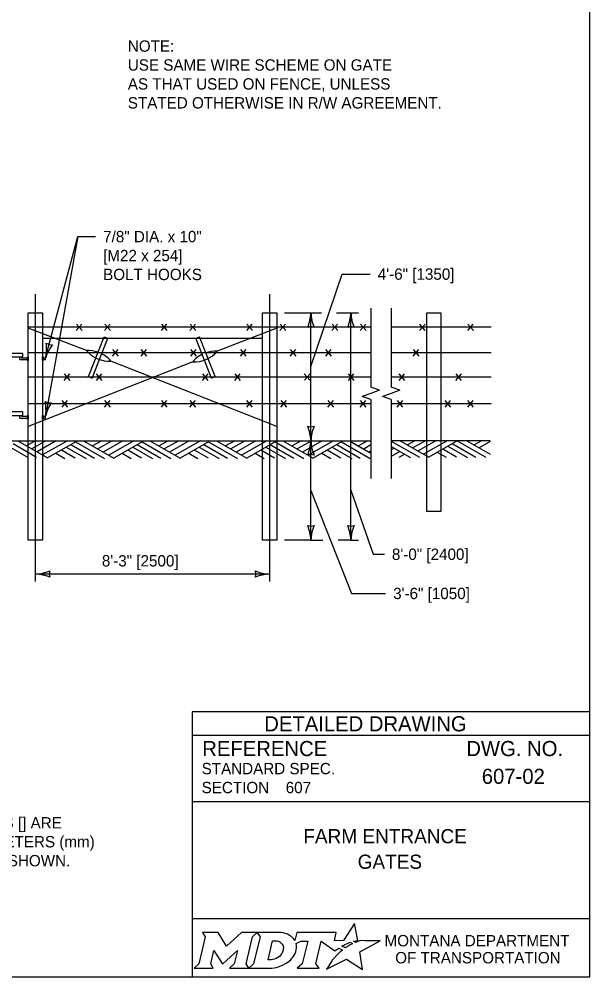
# Model space of a CAD drawing. Extents: x 49991.4 to 50021, y 49987.6 to 50011.4.
# Drawn here: x 50005.6 to 50008.61, y 50000.06 to 50005.12 of the extents above; entities that cross this region are included whole.
import ezdxf

# ---------------------------------------------------------------- set-up
doc = ezdxf.new("R2010")
doc.units = 0
for name, color, linetype in [('Level 1', 7, 'Continuous'), ('Level 2', 7, 'Continuous'), ('Level 3', 7, 'Continuous'), ('Level 4', 7, 'Continuous'), ('Level 5', 7, 'Continuous'), ('Level 6', 7, 'Continuous')]:
    doc.layers.add(name, color=color, linetype=linetype)

msp = doc.modelspace()

# ---------------------------------------------------------------- linework, layer by layer
at = {"layer": 'Level 1'}
for p, q in [((50005.6494, 50003.5711), (50005.7244, 50003.5711)), ((50005.6494, 50002.8961), (50005.6494, 50003.5711)), ((50005.7244, 50003.5711), (50005.7244, 50002.8961)), ((50006.8869, 50003.5711), (50006.9619, 50003.5711)), ((50006.8869, 50002.8961), (50006.8869, 50003.5711)), ((50006.9619, 50003.5711), (50006.9619, 50002.8961)), ((50007.7534, 50002.8961), (50007.7534, 50003.5711)), ((50007.7534, 50003.5711), (50007.8284, 50003.5711)), ((50007.8284, 50003.5711), (50007.8284, 50002.8961)), ((50007.4579, 50003.4961), (50005.6494, 50003.4961)), ((50005.9575, 50003.3719), (50005.6494, 50003.4906)), ((50006.8869, 50003.4961), (50005.7244, 50003.4961)), ((50005.9027, 50003.478), (50005.932, 50003.5127)), ((50005.9334, 50003.478), (50005.904, 50003.5127)), ((50006.0527, 50003.478), (50006.082, 50003.5127)), ((50006.0834, 50003.478), (50006.054, 50003.5127)), ((50006.3527, 50003.478), (50006.382, 50003.5127)), ((50006.3834, 50003.478), (50006.354, 50003.5127)), ((50006.5027, 50003.478), (50006.532, 50003.5127)), ((50006.5334, 50003.478), (50006.504, 50003.5127)), ((50006.9619, 50003.4909), (50006.6468, 50003.3684)), ((50006.8027, 50003.478), (50006.832, 50003.5127)), ((50006.8334, 50003.478), (50006.804, 50003.5127)), ((50006.9783, 50003.478), (50007.0076, 50003.5127)), ((50007.009, 50003.478), (50006.9796, 50003.5127)), ((50007.2527, 50003.478), (50007.282, 50003.5127)), ((50007.2834, 50003.478), (50007.254, 50003.5127)), ((50007.4027, 50003.478), (50007.432, 50003.5127)), ((50007.4334, 50003.478), (50007.404, 50003.5127)), ((50008.0929, 50003.4961), (50007.5658, 50003.4961)), ((50007.715, 50003.478), (50007.7443, 50003.5127)), ((50007.7457, 50003.478), (50007.7163, 50003.5127)), ((50007.97, 50003.478), (50007.9993, 50003.5127)), ((50008.0007, 50003.478), (50007.9713, 50003.5127)), ((50006.8869, 50003.4361), (50005.7244, 50003.4361)), ((50005.9674, 50003.2345), (50006.0506, 50003.4445)), ((50005.986, 50003.2271), (50006.0692, 50003.4371)), ((50006.0506, 50003.4445), (50006.0692, 50003.4371)), ((50006.5344, 50003.4371), (50006.553, 50003.4445)), ((50006.6177, 50003.2271), (50006.5344, 50003.4371)), ((50006.6362, 50003.2345), (50006.553, 50003.4445)), ((50006.0948, 50003.343), (50006.1242, 50003.3777)), ((50006.1255, 50003.343), (50006.0962, 50003.3777)), ((50006.2448, 50003.343), (50006.2742, 50003.3777)), ((50006.2755, 50003.343), (50006.2462, 50003.3777)), ((50006.5073, 50003.343), (50006.5367, 50003.3777)), ((50006.538, 50003.343), (50006.5087, 50003.3777)), ((50006.7698, 50003.343), (50006.7992, 50003.3777)), ((50006.8005, 50003.343), (50006.7712, 50003.3777)), ((50007.0331, 50003.343), (50007.0625, 50003.3777)), ((50007.0638, 50003.343), (50007.0345, 50003.3777)), ((50007.2198, 50003.343), (50007.2492, 50003.3777)), ((50007.2505, 50003.343), (50007.2212, 50003.3777)), ((50007.6821, 50003.343), (50007.7115, 50003.3777)), ((50007.7128, 50003.343), (50007.6835, 50003.3777)), ((50005.6052, 50003.3246), (50005.6052, 50003.3389)), ((50005.6052, 50003.3246), (50005.6494, 50003.3246)), ((50005.6146, 50003.334), (50005.6146, 50003.3389)), ((50005.6146, 50003.334), (50005.6494, 50003.334)), ((50007.4579, 50003.3611), (50005.6494, 50003.3611)), ((50005.7244, 50003.334), (50005.7413, 50003.334)), ((50005.7244, 50003.3246), (50005.7413, 50003.3246)), ((50005.7413, 50003.3246), (50005.7413, 50003.334)), ((50006.9619, 50002.9711), (50006.086, 50003.3168)), ((50008.0929, 50003.3611), (50007.5658, 50003.3611)), ((50006.5184, 50003.3133), (50005.6494, 50002.9711)), ((50007.4579, 50003.2321), (50005.6494, 50003.2321)), ((50005.8398, 50003.214), (50005.8692, 50003.2487)), ((50005.8705, 50003.214), (50005.8412, 50003.2487)), ((50005.9674, 50003.2345), (50005.986, 50003.2271)), ((50006.0092, 50003.214), (50006.0386, 50003.2487)), ((50006.0399, 50003.214), (50006.0106, 50003.2487)), ((50006.5692, 50003.214), (50006.5986, 50003.2487)), ((50006.5999, 50003.214), (50006.5706, 50003.2487)), ((50006.6177, 50003.2271), (50006.6362, 50003.2345)), ((50006.7398, 50003.214), (50006.7692, 50003.2487)), ((50006.7705, 50003.214), (50006.7412, 50003.2487)), ((50007.1359, 50003.2154), (50007.1066, 50003.2501)), ((50007.1077, 50003.2154), (50007.1371, 50003.2501)), ((50007.3398, 50003.214), (50007.3692, 50003.2487)), ((50007.3705, 50003.214), (50007.3412, 50003.2487)), ((50008.0929, 50003.2321), (50007.5658, 50003.2321)), ((50007.6071, 50003.214), (50007.6365, 50003.2487)), ((50007.6378, 50003.214), (50007.6085, 50003.2487)), ((50007.9071, 50003.214), (50007.9365, 50003.2487)), ((50007.9378, 50003.214), (50007.9085, 50003.2487)), ((50007.4579, 50003.0911), (50005.6494, 50003.0911)), ((50005.8277, 50003.073), (50005.857, 50003.1077)), ((50005.8584, 50003.073), (50005.829, 50003.1077)), ((50006.0527, 50003.073), (50006.082, 50003.1077)), ((50006.0834, 50003.073), (50006.054, 50003.1077)), ((50006.3527, 50003.073), (50006.382, 50003.1077)), ((50006.3834, 50003.073), (50006.354, 50003.1077)), ((50006.5027, 50003.073), (50006.532, 50003.1077)), ((50006.5334, 50003.073), (50006.504, 50003.1077)), ((50006.8027, 50003.073), (50006.832, 50003.1077)), ((50006.8334, 50003.073), (50006.804, 50003.1077)), ((50006.9833, 50003.073), (50007.0126, 50003.1077)), ((50007.014, 50003.073), (50006.9846, 50003.1077)), ((50007.2318, 50003.073), (50007.2611, 50003.1077)), ((50007.2625, 50003.073), (50007.2331, 50003.1077)), ((50007.4027, 50003.073), (50007.432, 50003.1077)), ((50007.4334, 50003.073), (50007.404, 50003.1077)), ((50008.0929, 50003.0911), (50007.5658, 50003.0911)), ((50007.5972, 50003.073), (50007.6265, 50003.1077)), ((50007.6279, 50003.073), (50007.5985, 50003.1077)), ((50007.85, 50003.073), (50007.8793, 50003.1077)), ((50007.8807, 50003.073), (50007.8513, 50003.1077)), ((50007.97, 50003.073), (50007.9993, 50003.1077)), ((50008.0007, 50003.073), (50007.9713, 50003.1077)), ((50005.6052, 50003.0156), (50005.6052, 50003.0299)), ((50005.6052, 50003.0156), (50005.6494, 50003.0156)), ((50005.6146, 50003.025), (50005.6146, 50003.0299)), ((50005.6146, 50003.025), (50005.6494, 50003.025)), ((50005.7244, 50003.025), (50005.7413, 50003.025)), ((50005.7244, 50003.0156), (50005.7413, 50003.0156)), ((50005.7413, 50003.0156), (50005.7413, 50003.025)), ((50004.5739, 50002.8961), (50007.4579, 50002.8961)), ((50005.5455, 50002.8676), (50005.6495, 50002.8075)), ((50005.5692, 50002.8812), (50005.6935, 50002.8094)), ((50005.5941, 50002.8961), (50005.7517, 50002.8051)), ((50005.686, 50002.8961), (50005.64, 50002.8696)), ((50005.742, 50002.8961), (50005.668, 50002.8534)), ((50005.7973, 50002.8961), (50005.6957, 50002.8375)), ((50005.8563, 50002.8961), (50005.7252, 50002.8204)), ((50005.8998, 50002.8906), (50005.7517, 50002.8051)), ((50005.8504, 50002.8621), (50005.9544, 50002.802)), ((50005.8741, 50002.8757), (50005.9984, 50002.8039)), ((50005.899, 50002.8906), (50006.0512, 50002.8027)), ((50005.9405, 50002.8961), (50006.1005, 50002.8037)), ((50006.0371, 50002.8961), (50005.9888, 50002.8682)), ((50006.0931, 50002.8961), (50006.0167, 50002.8521)), ((50006.1484, 50002.8961), (50006.0444, 50002.8361)), ((50006.2074, 50002.8961), (50006.074, 50002.819)), ((50006.2509, 50002.8906), (50006.1005, 50002.8037)), ((50006.2015, 50002.8621), (50006.3055, 50002.802)), ((50006.2252, 50002.8757), (50006.3495, 50002.8039)), ((50006.2501, 50002.8906), (50006.4023, 50002.8027)), ((50006.2916, 50002.8961), (50006.4516, 50002.8037)), ((50006.3882, 50002.8961), (50006.3399, 50002.8682)), ((50006.4442, 50002.8961), (50006.3678, 50002.8521)), ((50006.4995, 50002.8961), (50006.3955, 50002.8361)), ((50006.5585, 50002.8961), (50006.4251, 50002.819)), ((50006.602, 50002.8906), (50006.4516, 50002.8037)), ((50006.5526, 50002.8621), (50006.6566, 50002.802)), ((50006.5763, 50002.8757), (50006.7006, 50002.8039)), ((50006.6012, 50002.8906), (50006.7534, 50002.8027)), ((50006.6427, 50002.8961), (50006.8027, 50002.8037)), ((50006.7393, 50002.8961), (50006.691, 50002.8682)), ((50006.7953, 50002.8961), (50006.7189, 50002.8521)), ((50006.8506, 50002.8961), (50006.7466, 50002.8361)), ((50006.9096, 50002.8961), (50006.7762, 50002.819)), ((50006.9531, 50002.8906), (50006.8027, 50002.8037)), ((50006.9037, 50002.8621), (50007.0077, 50002.802)), ((50006.9274, 50002.8757), (50007.0517, 50002.8039)), ((50006.9523, 50002.8906), (50007.1045, 50002.8027)), ((50006.9938, 50002.8961), (50007.1537, 50002.8037)), ((50007.0904, 50002.8961), (50007.0421, 50002.8682)), ((50007.1464, 50002.8961), (50007.07, 50002.8521)), ((50007.2017, 50002.8961), (50007.0976, 50002.8362)), ((50007.2607, 50002.8961), (50007.1273, 50002.819)), ((50007.3038, 50002.8904), (50007.1537, 50002.8037)), ((50007.2548, 50002.8621), (50007.3588, 50002.802)), ((50007.2784, 50002.8757), (50007.4028, 50002.8039)), ((50007.3034, 50002.8906), (50007.4556, 50002.8027)), ((50007.3449, 50002.8961), (50007.4579, 50002.8308)), ((50007.4415, 50002.8961), (50007.3931, 50002.8682)), ((50007.4579, 50002.8733), (50007.4211, 50002.852)), ((50008.0891, 50002.8961), (50007.5658, 50002.8961)), ((50007.5658, 50002.894), (50007.7144, 50002.8082)), ((50007.5658, 50002.8655), (50007.6673, 50002.8069)), ((50007.6132, 50002.8961), (50007.7637, 50002.8092)), ((50007.6907, 50002.8961), (50007.652, 50002.8737)), ((50007.7468, 50002.8961), (50007.6799, 50002.8576)), ((50007.802, 50002.8961), (50007.7076, 50002.8416)), ((50007.8611, 50002.8961), (50007.7372, 50002.8245)), ((50007.9141, 50002.8961), (50007.7637, 50002.8092)), ((50007.8647, 50002.8676), (50007.9687, 50002.8075)), ((50007.8884, 50002.8812), (50008.0127, 50002.8094)), ((50007.9133, 50002.8961), (50008.0655, 50002.8082)), ((50007.9643, 50002.8961), (50008.0891, 50002.824)), ((50008.0418, 50002.8961), (50008.0031, 50002.8737)), ((50008.0891, 50002.891), (50008.031, 50002.8576)), ((50005.7948, 50002.83), (50005.8419, 50002.8027)), ((50005.8241, 50002.8469), (50005.8963, 50002.8051)), ((50006.1459, 50002.83), (50006.193, 50002.8027)), ((50006.1752, 50002.8469), (50006.2474, 50002.8051)), ((50006.497, 50002.83), (50006.5441, 50002.8027)), ((50006.5263, 50002.8469), (50006.5985, 50002.8051)), ((50006.8481, 50002.83), (50006.8952, 50002.8027)), ((50006.8774, 50002.8469), (50006.9496, 50002.8051)), ((50007.1992, 50002.83), (50007.2463, 50002.8027)), ((50007.2284, 50002.8469), (50007.3007, 50002.8051)), ((50007.4579, 50002.8415), (50007.4486, 50002.8361)), ((50007.5816, 50002.8564), (50007.5658, 50002.8472)), ((50007.6112, 50002.8393), (50007.5658, 50002.8131)), ((50007.6376, 50002.824), (50007.6069, 50002.8063)), ((50007.8091, 50002.8355), (50007.8562, 50002.8082)), ((50007.8384, 50002.8524), (50007.9106, 50002.8106))]:
    msp.add_line(p, q, dxfattribs=at)
for points in [[(50008.6146, 50011.2628), (50000.3356, 50011.2628), (50000.3356, 50000.0624), (50008.6146, 50000.0624)], [(50005.621, 50003.3389), (50005.621, 50003.3573), (50005.5547, 50003.3573), (50005.5547, 50003.3389)], [(50005.6494, 50003.3386), (50005.6494, 50003.3193), (50005.645, 50003.3193), (50005.645, 50003.3386)], [(50005.7288, 50003.3388), (50005.7288, 50003.3195), (50005.7244, 50003.3195), (50005.7244, 50003.3388)], [(50005.621, 50003.0299), (50005.621, 50003.0483), (50005.5547, 50003.0483), (50005.5547, 50003.0299)], [(50005.6494, 50003.0296), (50005.6494, 50003.0103), (50005.645, 50003.0103), (50005.645, 50003.0296)], [(50005.7288, 50003.0298), (50005.7288, 50003.0105), (50005.7244, 50003.0105), (50005.7244, 50003.0298)]]:
    msp.add_lwpolyline(points, close=True, dxfattribs=at)
for centre, start, end in [((50005.9672, 50003.2172), 70.692, 93.5951), ((50006.0763, 50003.4716), 220.0078, 273.5951), ((50006.528, 50003.468), 266.4347, 320.0376), ((50006.6372, 50003.2137), 86.4347, 109.12), ((50005.9672, 50003.2172), 40.0078, 63.2871), ((50006.6372, 50003.2137), 116.511, 140.0376)]:
    msp.add_arc(centre, 0.155, start, end, dxfattribs=at)
at = {"layer": 'Level 2'}
for p, q in [((50008.6146, 50001.4624), (50006.5146, 50001.4624)), ((50006.5146, 50001.4624), (50006.5146, 50000.0624)), ((50008.6146, 50001.3374), (50006.5146, 50001.3374)), ((50008.2507, 50001.1223), (50008.2507, 50001.1223)), ((50007.0089, 50001.0629), (50007.0089, 50001.0629)), ((50008.6146, 50000.9874), (50006.5146, 50000.9874)), ((50007.5646, 50000.7383), (50007.5646, 50000.7383)), ((50008.6146, 50000.3693), (50006.5146, 50000.3693))]:
    msp.add_line(p, q, dxfattribs=at)
for points in [[(50007.3771, 50000.2447), (50007.3668, 50000.2503), (50007.3784, 50000.2531), (50007.39, 50000.2551), (50007.3726, 50000.3452), (50007.3131, 50000.2539), (50007.2658, 50000.2532), (50007.2761, 50000.2973), (50007.0669, 50000.2974), (50007.0568, 50000.2549), (50007.051, 50000.2632)], [(50006.5701, 50000.2974), (50006.5842, 50000.274), (50006.5507, 50000.1307), (50006.525, 50000.1082), (50006.6266, 50000.1082), (50006.6131, 50000.131), (50006.6293, 50000.2011), (50006.673, 50000.1321), (50006.6783, 50000.1321), (50006.7534, 50000.2016), (50006.737, 50000.1305), (50006.7123, 50000.1085), (50006.8139, 50000.1085), (50006.8001, 50000.1318), (50006.8333, 50000.2742)], [(50006.8333, 50000.2742), (50006.8586, 50000.2974), (50006.7762, 50000.2974), (50006.6966, 50000.2244), (50006.6521, 50000.2971), (50006.5701, 50000.2974)], [(50006.9722, 50000.2974), (50006.8586, 50000.2974), (50006.8733, 50000.2745), (50006.8394, 50000.1307), (50006.8139, 50000.1085), (50006.9245, 50000.1085)], [(50006.9962, 50000.2107), (50006.995, 50000.2026), (50006.9918, 50000.1933), (50006.9876, 50000.1851), (50006.982, 50000.1776), (50006.9755, 50000.1707), (50006.9676, 50000.1644), (50006.9593, 50000.1597), (50006.9502, 50000.1558), (50006.9411, 50000.1535), (50006.9319, 50000.1526), (50006.916, 50000.1526), (50006.9396, 50000.2526), (50006.9556, 50000.2526), (50006.9632, 50000.252), (50006.9708, 50000.2501), (50006.9774, 50000.2471), (50006.9835, 50000.2429), (50006.9883, 50000.2379), (50006.992, 50000.2319), (50006.9947, 50000.2257), (50006.9963, 50000.2183), (50006.9963, 50000.2153), (50006.9962, 50000.2107)], [(50007.0636, 50000.2383), (50007.0882, 50000.2514), (50007.1251, 50000.2514), (50007.0965, 50000.1309), (50007.069, 50000.1082), (50007.1852, 50000.1082), (50007.1682, 50000.1311), (50007.1964, 50000.2513), (50007.2677, 50000.1996), (50007.2888, 50000.2147), (50007.3085, 50000.2038)], [(50007.2527, 50000.1479), (50007.2374, 50000.1235), (50007.2327, 50000.116), (50007.2269, 50000.1074), (50007.2246, 50000.1031), (50007.3299, 50000.1562), (50007.4138, 50000.1011), (50007.4007, 50000.1938), (50007.5076, 50000.2522), (50007.4583, 50000.253), (50007.4282, 50000.2534), (50007.4074, 50000.2537), (50007.4006, 50000.2522), (50007.3957, 50000.251), (50007.3873, 50000.2487), (50007.3771, 50000.2447)], [(50007.3267, 50000.2171), (50007.3243, 50000.2154), (50007.306, 50000.225), (50007.3163, 50000.2307), (50007.3204, 50000.2329), (50007.329, 50000.2369), (50007.3347, 50000.2395), (50007.3426, 50000.2425), (50007.3499, 50000.2452), (50007.3617, 50000.2378), (50007.3577, 50000.2357), (50007.3531, 50000.2332), (50007.3489, 50000.231), (50007.3439, 50000.2281), (50007.342, 50000.227), (50007.3393, 50000.2254), (50007.3368, 50000.224), (50007.3345, 50000.2224), (50007.3319, 50000.2206), (50007.3292, 50000.2188), (50007.3267, 50000.2171)], [(50006.9702, 50000.1158), (50006.9786, 50000.1184), (50006.9916, 50000.1238), (50007.012, 50000.1348)], [(50007.2666, 50000.164), (50007.2666, 50000.164)]]:
    msp.add_lwpolyline(points, dxfattribs=at)
for centre, radius, start, end in [((50006.9953, 50000.219), 0.0709, 339.5329, 15.8582), ((50006.9513, 50000.2363), 0.1183, 300.9103, 339.1383)]:
    msp.add_arc(centre, radius, start, end, dxfattribs=at)
for centre, major_axis, ratio, start_param, end_param in [((50006.9701, 50000.25), (0.0834, -0.0037), 0.568097, 0.61298, 1.570796), ((50007.0257, 50000.2573), (0.0361, -0.0295), 0.469099, 1.225588, 1.570796), ((50007.2764, 50000.1742), (-0.0098, -0.0102), 0.016458, 3.141593, 6.279097), ((50007.2974, 50000.1941), (-0.0112, -0.0097), 0.021651, 3.157348, 6.283185), ((50007.2597, 50000.1559), (-0.00694, -0.00806), 0.008222, 0, 3.137361), ((50006.9248, 50000.2568), (0, 0.1484), 0.987302, 3.139398, 3.456847)]:
    msp.add_ellipse(centre, major_axis=major_axis, ratio=ratio, start_param=start_param, end_param=end_param, dxfattribs=at)
at = {"layer": 'Level 3'}
for p, q in [((50005.7413, 50003.334), (50005.9113, 50003.9746)), ((50005.9113, 50003.9746), (50005.7413, 50003.025)), ((50005.9113, 50003.9746), (50006.0048, 50003.9746)), ((50007.0019, 50003.5711), (50007.1974, 50003.5711)), ((50007.1418, 50002.8961), (50007.1418, 50003.5711)), ((50007.2774, 50003.5712), (50007.393, 50003.5711)), ((50007.353, 50002.3711), (50007.353, 50003.5711)), ((50007.1418, 50002.3711), (50007.1418, 50002.8961)), ((50007.1418, 50002.3711), (50007.0019, 50002.3711)), ((50007.1418, 50002.3711), (50007.205, 50002.3711)), ((50007.353, 50002.3711), (50007.2851, 50002.3711)), ((50007.353, 50002.3711), (50007.393, 50002.3711)), ((50006.9244, 50002.1911), (50005.6869, 50002.1911))]:
    msp.add_line(p, q, dxfattribs=at)
for points in [[(50007.1418, 50003.2878), (50007.3067, 50003.7765), (50007.455, 50003.7765)], [(50007.1418, 50002.6336), (50007.3562, 50002.0887), (50007.5361, 50002.0887), (50007.5361, 50002.0887)], [(50007.353, 50002.6342), (50007.4701, 50002.2958), (50007.5297, 50002.2958)]]:
    msp.add_lwpolyline(points, dxfattribs=at)
for centre, radius, start, end in [((50006.9197, 50003.5803), 0.2223, 337.456, 357.6395), ((50007.3745, 50003.5826), 0.233, 182.8273, 202.0772), ((50007.1309, 50003.5803), 0.2223, 337.456, 357.6395), ((50007.5857, 50003.5826), 0.233, 182.8273, 202.0772), ((50007.1418, 50003.4429), 0.0548, 72.1388, 107.8612), ((50007.353, 50003.4429), 0.0548, 72.1388, 107.8612), ((50005.5134, 50003.3826), 0.233, 347.9649, 7.2148), ((50005.5134, 50003.3826), 0.233, 347.9649, 7.2148), ((50005.9537, 50003.2682), 0.2223, 142.5936, 162.7772), ((50005.9537, 50003.2682), 0.2223, 142.5936, 162.7772), ((50005.7742, 50003.4579), 0.0548, 237.2765, 272.9988), ((50005.7742, 50003.4579), 0.0548, 237.2765, 272.9988), ((50005.7639, 50003.1512), 0.0548, 241.9891, 277.7115), ((50005.5102, 50003.0547), 0.233, 352.6776, 11.9274), ((50005.9583, 50002.9768), 0.2223, 147.3063, 167.4898), ((50007.1418, 50003.0243), 0.0548, 252.1388, 287.8612), ((50006.9091, 50002.8846), 0.233, 2.8273, 22.0772), ((50007.3639, 50002.8869), 0.2223, 157.456, 177.6395), ((50006.9197, 50002.9053), 0.2223, 337.456, 357.6395), ((50007.3745, 50002.9076), 0.233, 182.8273, 202.0772), ((50007.1418, 50002.7679), 0.0548, 72.1388, 107.8612), ((50007.1418, 50002.4993), 0.0548, 252.1388, 287.8612), ((50006.9091, 50002.3596), 0.233, 2.8273, 22.0772), ((50007.3639, 50002.362), 0.2223, 157.456, 177.6395), ((50007.353, 50002.4993), 0.0548, 252.1388, 287.8612), ((50007.1202, 50002.3596), 0.233, 2.8273, 22.0772), ((50007.5751, 50002.362), 0.2223, 157.456, 177.6395), ((50005.6754, 50002.4238), 0.233, 272.8273, 292.0772), ((50005.8151, 50002.1911), 0.0548, 162.1388, 197.8612), ((50006.9336, 50002.4132), 0.2223, 247.456, 267.6395), ((50006.7962, 50002.1911), 0.0548, 342.1388, 17.8612), ((50005.6777, 50001.969), 0.2223, 67.456, 87.6395), ((50006.9359, 50001.9584), 0.233, 92.8273, 112.0772)]:
    msp.add_arc(centre, radius, start, end, dxfattribs=at)
at = {"layer": 'Level 4'}
for p, q in [((50005.6494, 50002.3711), (50005.6494, 50002.8961)), ((50005.7244, 50002.8961), (50005.7244, 50002.3711)), ((50006.8869, 50002.3711), (50006.8869, 50002.8961)), ((50006.9619, 50002.8961), (50006.9619, 50002.3711)), ((50007.7534, 50002.5211), (50007.7534, 50002.8961)), ((50007.8284, 50002.8961), (50007.8284, 50002.5211)), ((50007.8284, 50002.5211), (50007.7534, 50002.5211)), ((50005.7244, 50002.3711), (50005.6494, 50002.3711)), ((50006.9619, 50002.3711), (50006.8869, 50002.3711))]:
    msp.add_line(p, q, dxfattribs=at)
at = {"layer": 'Level 5'}
for p, q in [((50005.6869, 50002.1511), (50005.6869, 50003.6711)), ((50006.9244, 50002.1511), (50006.9244, 50003.6711))]:
    msp.add_line(p, q, dxfattribs=at)
at = {"layer": 'Level 6'}
for p, q in [((50007.4579, 50003.5961), (50007.4579, 50003.1785)), ((50007.5658, 50003.5961), (50007.5658, 50003.1785)), ((50007.5036, 50003.1623), (50007.4579, 50003.1785)), ((50007.5036, 50003.1623), (50007.4579, 50003.1461)), ((50007.6115, 50003.1623), (50007.5658, 50003.1785)), ((50007.6115, 50003.1623), (50007.5658, 50003.1461)), ((50007.4579, 50003.1461), (50007.4122, 50003.1299)), ((50007.4579, 50003.1137), (50007.4122, 50003.1299)), ((50007.4579, 50003.1137), (50007.4579, 50002.6961)), ((50007.5658, 50003.1461), (50007.5201, 50003.1299)), ((50007.5658, 50003.1137), (50007.5201, 50003.1299)), ((50007.5658, 50003.1137), (50007.5658, 50002.6961))]:
    msp.add_line(p, q, dxfattribs=at)

# ---------------------------------------------------------------- texts
at = {"layer": 'Level 2'}
for s, height, p in [('NOTE:', 0.06, (50006.1751, 50004.9516)), ('USE SAME WIRE SCHEME ON GATE', 0.06, (50006.1751, 50004.8516)), ('AS THAT USED ON FENCE, UNLESS', 0.06, (50006.1751, 50004.7516)), ('STATED OTHERWISE IN R/W AGREEMENT.', 0.06, (50006.1751, 50004.6516)), ('7/8" DIA. x 10"', 0.06, (50006.0448, 50003.9446)), ('[M22 x 254]', 0.06, (50006.0448, 50003.8446)), ('BOLT HOOKS', 0.06, (50006.0448, 50003.7446)), ('4\'-6" [1350]', 0.06, (50007.495, 50003.7465)), ('8\'-0" [2400]', 0.06, (50007.5697, 50002.2658)), ('8\'-3" [2500]', 0.06, (50006.0381, 50002.2311)), ('3\'-6" [1050]', 0.06, (50007.5761, 50002.0587)), ('DETAILED DRAWING', 0.0799, (50006.8956, 50001.3599)), ('REFERENCE', 0.08, (50006.5682, 50001.229)), ('DWG. NO.', 0.08, (50007.9624, 50001.229)), ('STANDARD SPEC.', 0.06, (50006.5649, 50001.133)), ('607-02', 0.08, (50008.0441, 50001.0823)), ('SECTION', 0.06, (50006.5649, 50001.033)), ('607', 0.06, (50007.0089, 50001.0329)), ('UNITS SHOWN IN BRACKETS [] ARE', 0.06, (50004.4447, 50000.8465)), ('FARM ENTRANCE', 0.075, (50007.1017, 50000.7683)), ('METRIC AND ARE IN MILLIMETERS (mm)', 0.06, (50004.4447, 50000.7465)), ('UNLESS OTHER UNITS ARE SHOWN.', 0.06, (50004.4447, 50000.6465)), ('GATES', 0.075, (50007.3888, 50000.6333)), ('MONTANA DEPARTMENT', 0.06, (50007.5308, 50000.2236)), ('OF TRANSPORTATION', 0.06, (50007.587, 50000.1336))]:
    msp.add_text(s, height=height, dxfattribs=at).set_placement(p)

doc.saveas('drawing.dxf')
